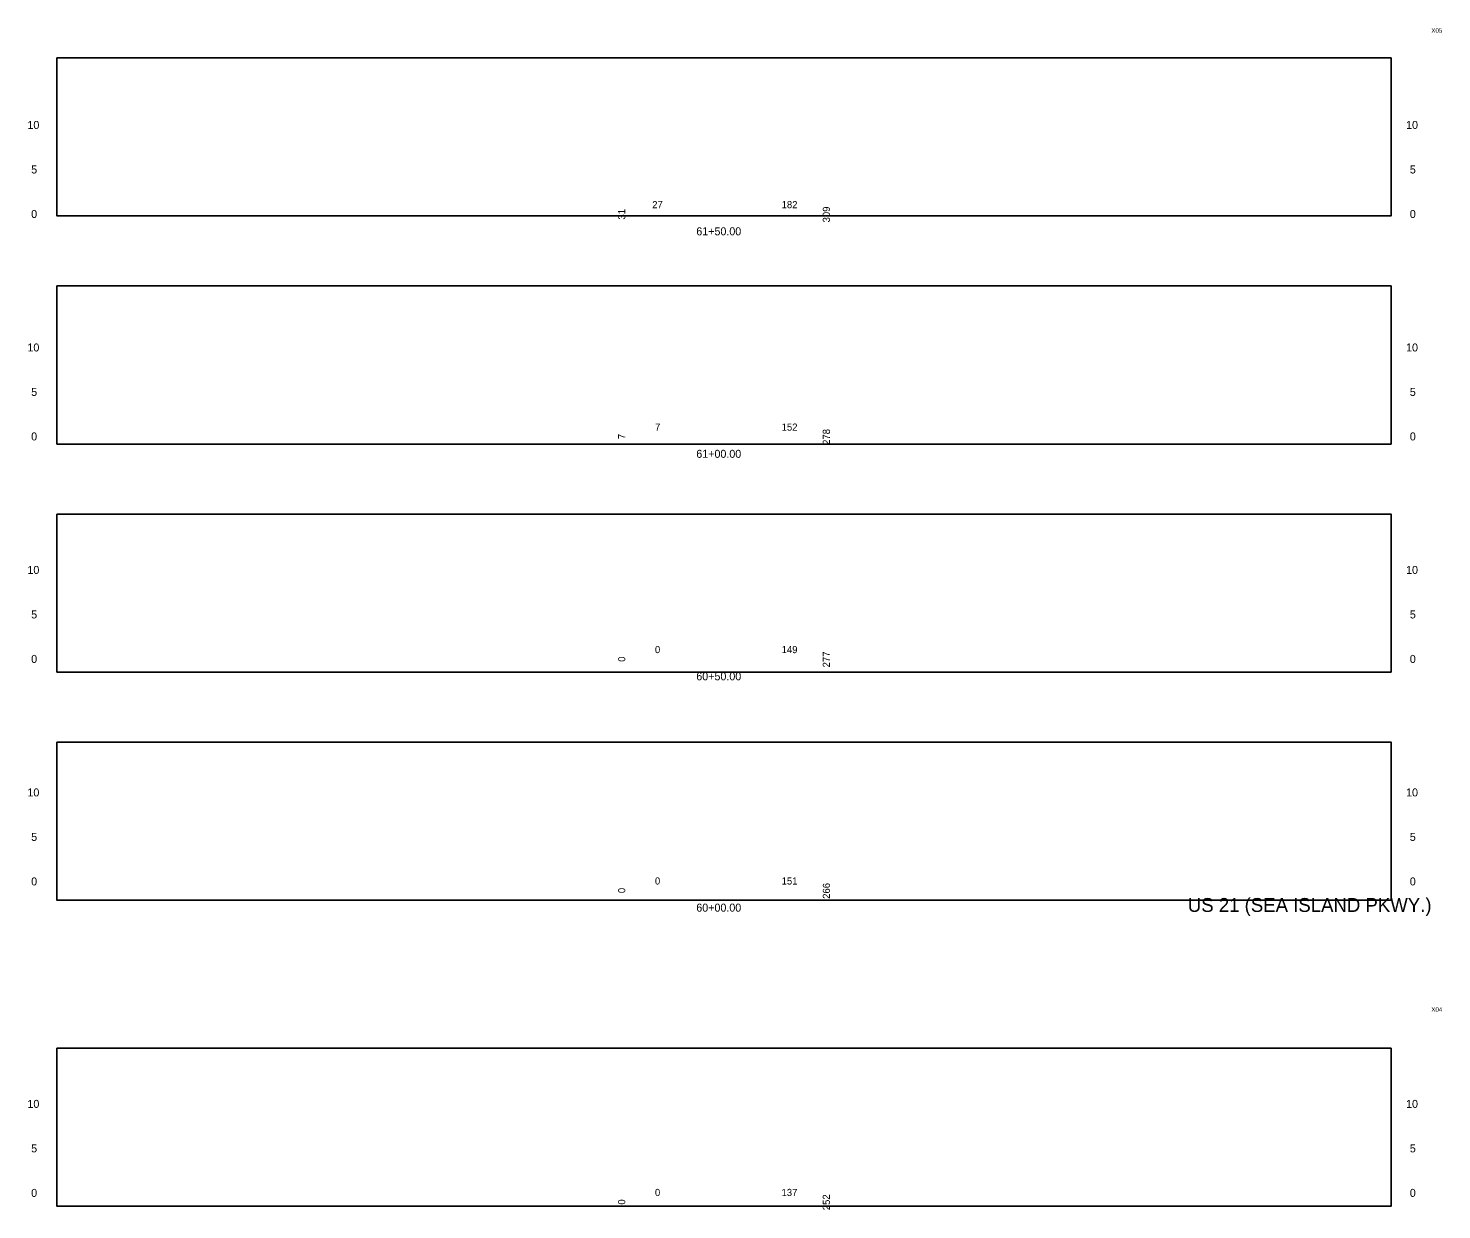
# Model space of a CAD drawing. Extents: x 971 to 1131, y 2203 to 6043.
# Drawn here: x 971.5 to 1130.4, y 2610.4 to 2743.2 of the extents above; entities that cross this region are included whole.
import ezdxf

# ---------------------------------------------------------------- set-up
doc = ezdxf.new("R2010")
doc.units = 0
for name, color, linetype in [('RD_SHT_Misc1', 7, 'Continuous'), ('RD_SHT_ShtClip', 7, 'Continuous'), ('RD_SHT_TX', 7, 'Continuous'), ('RD_XS_TX_Station', 7, 'Continuous')]:
    doc.layers.add(name, color=color, linetype=linetype)

msp = doc.modelspace()

# ---------------------------------------------------------------- linework, layer by layer
at = {"layer": 'RD_SHT_ShtClip'}
for points in [[(974.73, 2739.86), (1124.73, 2739.86), (1124.73, 2722.1), (974.73, 2722.1)], [(974.73, 2714.23), (1124.73, 2714.23), (1124.73, 2696.47), (974.73, 2696.47)], [(974.73, 2688.6), (1124.73, 2688.6), (1124.73, 2670.84), (974.73, 2670.84)], [(974.73, 2662.97), (1124.73, 2662.97), (1124.73, 2645.21), (974.73, 2645.21)], [(974.73, 2628.57), (1124.73, 2628.57), (1124.73, 2610.81), (974.73, 2610.81)]]:
    msp.add_lwpolyline(points, close=True, dxfattribs=at)

# ---------------------------------------------------------------- texts
at = {"layer": 'RD_SHT_Misc1'}
for s, p in [('27', (1041.66, 2722.97)), ('182', (1056.21, 2722.97)), ('7', (1041.98, 2697.97)), ('0', (1041.97, 2672.97)), ('149', (1056.21, 2672.97)), ('0', (1041.97, 2646.97)), ('151', (1056.21, 2646.97)), ('0', (1041.97, 2611.97)), ('137', (1056.2, 2611.97))]:
    msp.add_text(s, height=0.8, dxfattribs=at).set_placement(p)
for s, rotation, p in [('31', 90, (1038.63, 2721.69)), ('309', 90, (1061.64, 2721.37)), ('152', 360, (1056.21, 2697.97)), ('7', 90, (1038.63, 2697.01)), ('278', 90, (1061.64, 2696.37)), ('277', 90, (1061.64, 2671.37)), ('0', 90, (1038.63, 2672)), ('0', 90, (1038.63, 2646)), ('266', 90, (1061.64, 2645.36)), ('0', 90, (1038.63, 2611)), ('252', 90, (1061.64, 2610.37))]:
    msp.add_text(s, height=0.8, rotation=rotation, dxfattribs=at).set_placement(p)
at = {"layer": 'RD_SHT_TX'}
for s, p in [('X05', (1129.26, 2742.68)), ('X04', (1129.26, 2632.68))]:
    msp.add_text(s, height=0.5, rotation=360, dxfattribs=at).set_placement(p)
for s, height, p in [('10', 0.9, (971.42, 2731.87)), ('10', 0.9, (1126.42, 2731.87)), ('5', 0.9, (971.84, 2726.87)), ('5', 0.9, (1126.84, 2726.87)), ('0', 0.9, (971.84, 2721.87)), ('0', 0.9, (1126.84, 2721.87)), ('10', 0.9, (971.42, 2706.87)), ('10', 0.9, (1126.42, 2706.87)), ('5', 0.9, (971.84, 2701.87)), ('5', 0.9, (1126.84, 2701.87)), ('0', 0.9, (971.84, 2696.87)), ('0', 0.9, (1126.84, 2696.87)), ('10', 0.9, (971.42, 2681.87)), ('10', 0.9, (1126.42, 2681.87)), ('5', 0.9, (971.84, 2676.87)), ('5', 0.9, (1126.84, 2676.87)), ('0', 0.9, (971.84, 2671.87)), ('0', 0.9, (1126.84, 2671.87)), ('10', 0.9, (971.42, 2656.87)), ('10', 0.9, (1126.42, 2656.87)), ('5', 0.9, (971.84, 2651.87)), ('5', 0.9, (1126.84, 2651.87)), ('0', 0.9, (971.84, 2646.87)), ('0', 0.9, (1126.84, 2646.87)), ('US 21 (SEA ISLAND PKWY.)', 1.5625, (1101.88, 2643.89)), ('10', 0.9, (971.42, 2621.87)), ('10', 0.9, (1126.42, 2621.87)), ('5', 0.9, (971.84, 2616.87)), ('5', 0.9, (1126.84, 2616.87)), ('0', 0.9, (971.84, 2611.87)), ('0', 0.9, (1126.84, 2611.87))]:
    msp.add_text(s, height=height, dxfattribs=at).set_placement(p)
at = {"layer": 'RD_XS_TX_Station'}
for s, p in [('61+50.00', (1046.62, 2719.92)), ('61+00.00', (1046.62, 2694.92)), ('60+50.00', (1046.62, 2669.92)), ('60+00.00', (1046.62, 2643.92))]:
    msp.add_text(s, height=0.9, dxfattribs=at).set_placement(p)

doc.saveas('drawing.dxf')
